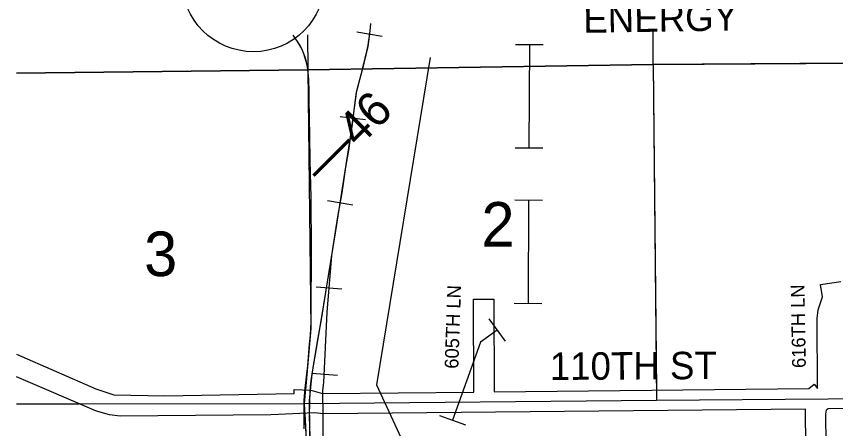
# Model space of a CAD drawing. Extents: x 10133 to 81668, y 5524 to 11018.
# Drawn here: x 15006.1 to 15305, y 9559.1 to 9709.4 of the extents above; entities that cross this region are included whole.
import ezdxf

# ---------------------------------------------------------------- set-up
doc = ezdxf.new("R2010")
doc.units = 0
doc.layers.add('Default', color=7, linetype='Continuous')

msp = doc.modelspace()

# ---------------------------------------------------------------- linework, layer by layer
at = {"layer": 'Default'}
for p, q in [((15130.36, 9703.73), (15139.6, 9702.16)), ((15188.21, 9699.17), (15198.28, 9699.12)), ((15124.2, 9672.93), (15133.5, 9671.74)), ((15188.04, 9661.5), (15198.12, 9661.45)), ((15119.57, 9642.24), (15128.8, 9640.64)), ((15187.94, 9642.48), (15198.01, 9642.43)), ((15115.45, 9610.82), (15124.8, 9610.12)), ((15187.76, 9604.81), (15197.85, 9604.76)), ((15178.52, 9599.12), (15184.44, 9590.98)), ((15113.86, 9579.36), (15123.21, 9578.66)), ((15160.46, 9563.96), (15169.95, 9560.55))]:
    msp.add_line(p, q, dxfattribs=at)
for points in [[(15113.23, 9548.58), (15113.09, 9569.21), (15114.01, 9579.08), (15117.37, 9599.15), (15122.56, 9630.47), (15127.97, 9665.35), (15130.36, 9682.2), (15132.97, 9692.32), (15134.39, 9698.4), (15135.13, 9704.09), (15135.4, 9706.84)], [(15238.47, 9691.82), (15238.38, 9704.32)], [(15238.47, 9691.82), (15238.38, 9704.32)], [(15112.47, 9689.85), (15112.47, 9689.85), (15112.31, 9690.91), (15112.07, 9692.14), (15111.76, 9693.36), (15111.39, 9694.56), (15110.97, 9695.75), (15110.49, 9696.91), (15109.95, 9698.05), (15109.36, 9699.16), (15108.71, 9700.23), (15107.87, 9701.45), (15107.03, 9702.57)], [(15111.06, 9559.05), (15111.09, 9566.67), (15111.08, 9568.24), (15111.07, 9569.53), (15111.49, 9573.79), (15111.89, 9577.95), (15112.38, 9582.02), (15113.09, 9589.94), (15113.37, 9593.21), (15113.59, 9597.96), (15113.62, 9601.44), (15113.65, 9606.31), (15113.74, 9618.82), (15113.74, 9629.74), (15113.62, 9637.54), (15113.59, 9643.42), (15113.25, 9656.71), (15113.15, 9665.74), (15112.97, 9679.03), (15112.89, 9681.73), (15112.75, 9686.52), (15112.48, 9689.85), (15112.32, 9690.91), (15112.07, 9692.14), (15111.77, 9693.36), (15111.4, 9694.56), (15110.97, 9695.75), (15110.49, 9696.91), (15109.95, 9698.05), (15108.72, 9700.24), (15107.87, 9701.45), (15107.04, 9702.57)], [(15112.25, 9702.64), (15112.48, 9689.85)], [(15112.25, 9702.64), (15112.48, 9689.85)], [(15134.98, 9702.94), (15134.72, 9701.41), (15134.46, 9699.88), (15134.26, 9698.83), (15134.06, 9697.77), (15133.66, 9695.99), (15133.25, 9694.21), (15132.75, 9692.18), (15132.25, 9690.16), (15130.74, 9684.32), (15130.12, 9681.68), (15129.59, 9678.11), (15128.56, 9670.08), (15127.66, 9663.33), (15127.33, 9661.28), (15126.23, 9654.44), (15124.82, 9645.1), (15123.41, 9636.99), (15121.71, 9626.22), (15121.05, 9622.23), (15118.87, 9608.85), (15117.24, 9598.93), (15115.88, 9590.83), (15114.53, 9582.82), (15113.65, 9577.44), (15113.3, 9574.61), (15113.1, 9572.42), (15113, 9569.01), (15112.94, 9563.56), (15113.1, 9556.38)], [(15134.98, 9702.94), (15134.72, 9701.41), (15134.46, 9699.88), (15134.26, 9698.83), (15134.06, 9697.77), (15133.66, 9695.99), (15133.25, 9694.21), (15132.75, 9692.18), (15132.25, 9690.16), (15130.74, 9684.32), (15130.12, 9681.68), (15129.59, 9678.11), (15128.56, 9670.08), (15127.66, 9663.33), (15127.33, 9661.28), (15126.23, 9654.44), (15124.82, 9645.1), (15123.41, 9636.99), (15121.71, 9626.22), (15121.05, 9622.23), (15119.35, 9601.52), (15118.1, 9575.91), (15117.76, 9573.08), (15117.87, 9563.35), (15117.93, 9548.72)], [(15006.1, 9688.72), (15112.48, 9689.85), (15238.47, 9691.82), (15363.32, 9692.72), (15488.7, 9694.26), (15611.84, 9694.7), (15738, 9696.54), (15862.97, 9698.38), (15945.75, 9699.07)], [(15945.75, 9699.07), (15862.97, 9698.38), (15738, 9696.54), (15611.84, 9694.7), (15488.7, 9694.26), (15363.32, 9692.72), (15238.47, 9691.82), (15112.48, 9689.85), (15006.1, 9688.72)], [(15193.26, 9699.15), (15193.08, 9661.48)], [(15006.1, 9688.72), (15112.48, 9689.85), (15238.47, 9691.82), (15331.16, 9692.49)], [(15157.06, 9694.37), (15137.44, 9575.03), (15165.13, 9515.43), (15164.7, 9475.57)], [(15238.47, 9691.82), (15363.32, 9692.72)], [(15238.47, 9691.82), (15331.16, 9692.49)], [(15006.1, 9688.72), (15112.48, 9689.85)], [(15006.1, 9688.72), (15112.48, 9689.85)], [(15112.48, 9689.85), (15113.48, 9595.58), (15111.08, 9568.24)], [(15112.48, 9689.85), (15113.48, 9595.58), (15111.52, 9573.25)], [(15112.48, 9689.85), (15238.47, 9691.82)], [(15112.48, 9689.85), (15238.47, 9691.82)], [(15238.47, 9691.82), (15239.6, 9573.26)], [(15238.47, 9691.82), (15239.64, 9569.51)], [(15192.99, 9642.45), (15192.81, 9604.78)], [(15107.39, 9571.89), (15107.43, 9573.39), (15113.55, 9573.2), (15117.74, 9571.96), (15172.96, 9572.38), (15172.82, 9606.36), (15180.32, 9606.25), (15180.46, 9572.5), (15295.23, 9573.74), (15297.15, 9575.28), (15298.41, 9573.79), (15298.25, 9599.32), (15298.56, 9602.46), (15300.18, 9607.22), (15299.49, 9611.61), (15306.9, 9612.78)], [(15181.48, 9595.05), (15175.38, 9590.61), (15165.21, 9562.25)], [(15006.1, 9586.21), (15035.06, 9573.67), (15041.62, 9571.46), (15060.31, 9571.04), (15107.39, 9571.89)], [(15294.44, 9511.68), (15293.97, 9566.22), (15118.19, 9564.46), (15114.91, 9564.88), (15098.94, 9564.18), (15043.94, 9563.63), (15040.05, 9564.12), (15035.32, 9565.44), (15006.1, 9578.06)], [(15239.64, 9569.51), (15364.83, 9570.52)], [(15006.1, 9568.2), (15111.08, 9568.24)], [(15006.1, 9568.2), (15028.91, 9568.21)], [(15111.08, 9568.24), (15239.64, 9569.51)], [(15111.08, 9568.24), (15117.95, 9443.49)], [(15111.28, 9564.51), (15112.92, 9534.81)], [(15361.12, 9566.75), (15302.29, 9566.34), (15301.55, 9565.91), (15301.29, 9564.37), (15301.93, 9510.93), (15300.65, 9507.31), (15297.74, 9504.66), (15295.03, 9503.54), (15292.63, 9503.35), (15182.35, 9502.29), (15181.33, 9501.38), (15181.2, 9496.37), (15182.08, 9447.13), (15253.56, 9447.66), (15257.46, 9447.55), (15259.31, 9447.01), (15261.5, 9445.81), (15276.42, 9432.96), (15278.59, 9429.74), (15282, 9422.24), (15284.16, 9419.65), (15301.86, 9405.94), (15304.21, 9403.72), (15306.35, 9400.78)]]:
    msp.add_lwpolyline(points, dxfattribs=at)
msp.add_circle((15092.58, 9722.55), 26.06, dxfattribs=at)

# ---------------------------------------------------------------- texts
for s, height, rotation, p in [('ENERGY', 10, 0.8677, (15212.99, 9703.38)), ('‒‒46', 12.5, 45, (15117.77, 9648.08)), ('2', 16.25, 0.0248, (15175.76, 9625.45)), ('3', 16.25, 0.024, (15052.71, 9614.71)), ('605TH LN', 5, 88, (15167.31, 9580.89)), ('616TH LN', 5, 91, (15294.11, 9581.25)), ('110TH ST', 10, 0.3175, (15200.72, 9576.85))]:
    msp.add_text(s, height=height, rotation=rotation, dxfattribs=at).set_placement(p)

doc.saveas('drawing.dxf')
